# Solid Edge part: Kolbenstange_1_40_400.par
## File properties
Username: ahadarics
Dokumentum tartalom típus: 0
Author: ahadarics
Last saved by: ahadarics
Revision: 88
Sűrűség: 0,000 kg/m^3
Pontosság: 0,990
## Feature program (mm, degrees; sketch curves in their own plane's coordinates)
base feature "unnamed BaseFeature 1"
thread "unnamed Thread 1"
chamfer "Letörés_1"  SetBackValue2 = 20 deg
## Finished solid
Body 1: solid body, 21 faces, 32 edges, 14 vertices.
  Faces by surface: plane 8, cylinder 5, cone 4, torus 4
  Edges by curve: circle 17, line 9, curve on surface 4, ellipse 2
Bounding box of the edges (mm; curved faces can reach further): 40.000 x 40.000 x 528.000, from (-20, -20, -78) to (20, 20, 450).
Cylindrical faces by radius (mm): R5 x1, R6 x1, R7.75 x1, R8 x1, R20 x1
Conical faces (half-angle, radius in mm at the cone's reference point): 20 deg R6 x1, 30 deg R7.875 x1, 45 deg R19.6 x1, 60 deg R5.5 x1
Toroidal faces (ring radius, tube radius in mm): R5.4 r0.4 x2, R6.55 r1.2 x2
Planar faces by outward normal: +x 1, +z 3, -x 1, -z 1, oblique 2
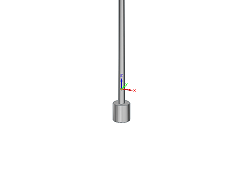
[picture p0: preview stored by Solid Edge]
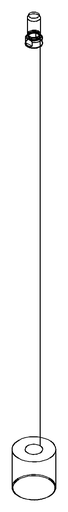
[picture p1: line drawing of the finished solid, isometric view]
